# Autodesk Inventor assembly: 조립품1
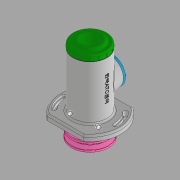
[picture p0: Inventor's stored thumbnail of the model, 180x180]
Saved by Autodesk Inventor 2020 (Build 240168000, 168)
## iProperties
Created: 2022-05
Part Number: 조립품1
Document SubType Name: Assembly
Designer: User
Author: User
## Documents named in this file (22)
- C:\Users\User\Desktop\720506V1038\조립품1.iam
- C:\Users\User\Desktop\720506V1038\본체.ipt
- C:\Users\User\Desktop\720506V1038\Ű 4 x 4.ipt
- C:\Users\User\Desktop\720506V1038\V-벨트풀리.ipt
- C:\Users\User\Desktop\720506V1038\개스킷.ipt
- C:\Users\User\Desktop\720506V1038\너트 M10.ipt
- C:\Users\User\Desktop\720506V1038\멈춤나사 M3.ipt
- C:\Users\User\Desktop\720506V1038\멈춤링 15 x 1.ipt
- C:\Users\User\Desktop\720506V1038\멈춤링 35 x 1.6.ipt
- C:\Users\User\Desktop\720506V1038\베어링 6202.ipt
- C:\Users\User\Desktop\720506V1038\볼트 M4 x 10.ipt
- C:\Users\User\Desktop\720506V1038\부시1.ipt
- C:\Users\User\Desktop\720506V1038\부시2.ipt
- C:\Users\User\Desktop\720506V1038\사이드 커버.ipt
- 사이드 커버.ipt
- C:\Users\User\Desktop\720506V1038\십자볼트 M3 x 10.ipt
- C:\Users\User\Desktop\720506V1038\오일 실 15 x 30 x 7.ipt
- C:\Users\User\Desktop\720506V1038\와셔 3 x 6.ipt
- C:\Users\User\Desktop\720506V1038\와셔 4 x 16.ipt
- C:\Users\User\Desktop\720506V1038\와셔 10 x 21.ipt
- C:\Users\User\Desktop\720506V1038\축.ipt
- C:\Users\User\Desktop\720506V1038\탑 커버.ipt
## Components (4 placed, 4 different names)
1. V-벨트풀리:1 — 각도:1, 플러쉬:1, 각도:2
2. 개스킷:1
3. ISO 4017 M4 x 10:1 — 각도:5, 각도:6
4. Ű 4 x 4:1 — 각도:1, 각도:3
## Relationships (6: Angle 5, Flush 1)
- 각도:1 [Angle]: V-벨트풀리:1 ↔ Ű 4 x 4:1
- 플러쉬:1 [Flush]: V-벨트풀리:1
- 각도:2 [Angle]: V-벨트풀리:1
- 각도:3 [Angle]: Ű 4 x 4:1
- 각도:5 [Angle]: ISO 4017 M4 x 10:1
- 각도:6 [Angle]: ISO 4017 M4 x 10:1
